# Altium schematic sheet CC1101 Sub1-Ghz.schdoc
size 297 x 209 mm; Symbol: Drawing-Symbol_A4; @Project Name: Hưhwwuey; @Page Count: 5; @Update Date: 2026-10-18; @Create Date: 2026-10-18; @Schematic Name: Schematic1; @Page No: 5; @Page Name: P1; Company: EasyEDA.com; Version: V1.0; Page Size: A4; Device: Drawing-Symbol_A4; @Create Time: 09:30:38; @Update Time: 09:30:38; Border: 1; Width: 1170; Height: 825; Region Start: 1; X Region Count: 6; Y Region Count: 4; Blade Width: 10; Title Block Position: 3; @Board Name: Board1
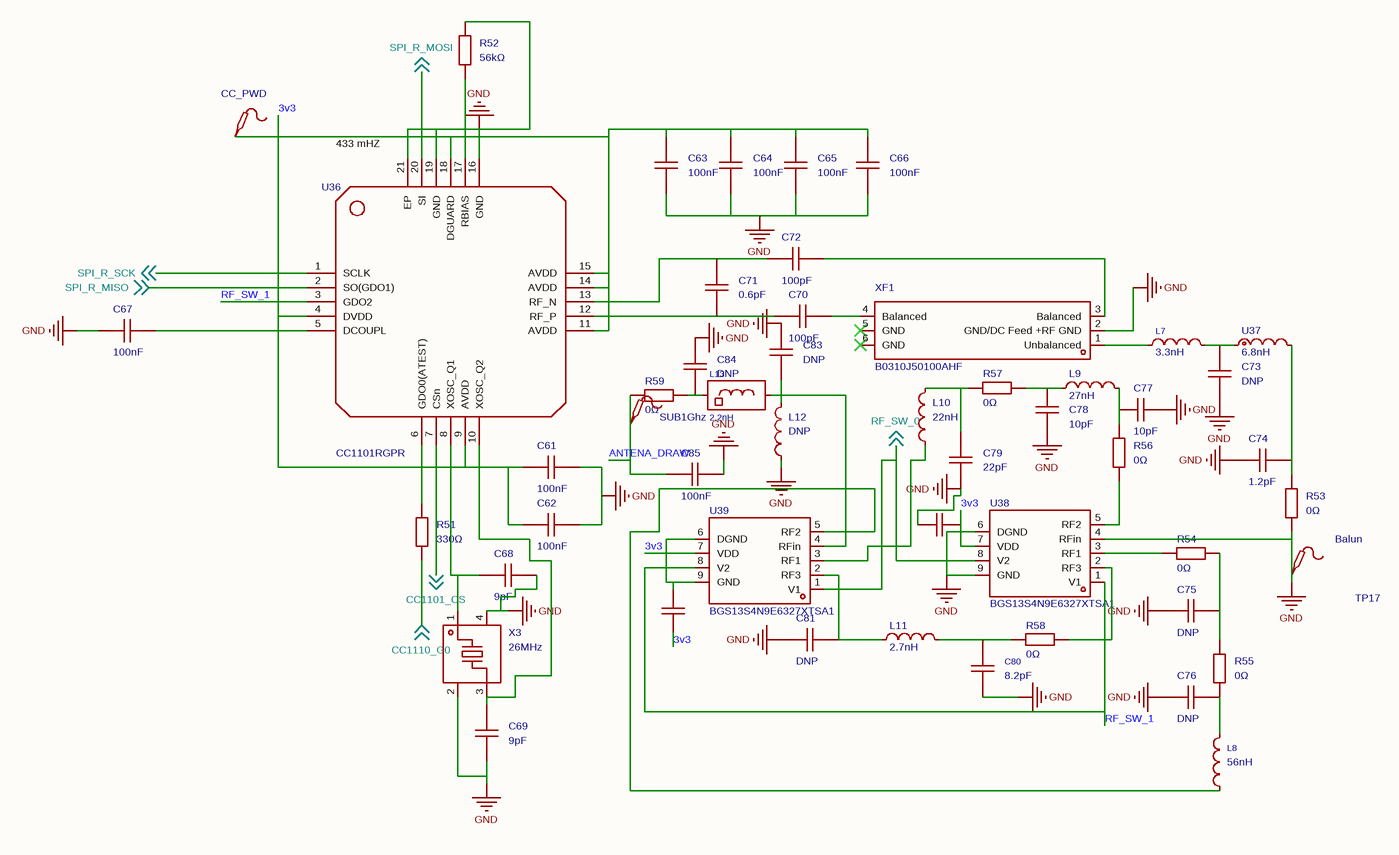
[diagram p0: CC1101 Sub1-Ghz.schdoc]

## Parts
C61  100nF  [C0402]
C62  100nF  [C0402]
C63  100nF  [C0402]
C64  100nF  [C0402]
C65  100nF  [C0402]
C66  100nF  [C0402]
C67  100nF  [C0402]
C68  9pF  [C0402]
C69  9pF  [C0402]
C70  100pF  [C0603]
C71  0.6pF  [C0201]
C72  100pF  [C0603]
C73  DNP  [C0402]
C74  1.2pF  [C0402]
C75  DNP  [C0402]
C76  DNP  [C0402]
C77  10pF  [C0603]
C78  10pF  [C0603]
C79  22pF  [C0402]
C80  8.2pF  [C0402]
C81  DNP  [C0402]
C82  10nF  [C0402]  (value not drawn)
C83  DNP  [C0402]
C84  DNP  [C0402]
C85  100nF  [C0402]
C86  10nF  [C0402]  (value not drawn)
L7  3.3nH  [L0402]
L8  56nH  [L0402]
L9  27nH  [L0402-RD]
L10  22nH  [L0402]
L11  2.7nH  [L0402]
L12  DNP  [L0402]
L13  2.2nH  [IND-SMD_L1.0-W0.5_LQG15HN1N6B02D]
R51  330Ω  [R0402]
R52  56kΩ  [R0402]
R53  0Ω  [R0201]
R54  0Ω  [R0402]
R55  0Ω  [R0402]
R56  0Ω  [R0402]
R57  0Ω  [R0402]
R58  0Ω  [R0402]
R59  0Ω  [R0402]
TP16  CC_PWD  [Test-Point-0.5mm]
TP17  Balun  [Test-Point-0.5mm]
TP18  SUB1Ghz  [Test-Point-0.5mm]
U36  CC1101RGPR  [QFN-20_L4.0-W4.0-P0.5-TL-EP]
U37  6.8nH  [L0402-RD]
U38  BGS13S4N9E6327XTSA1  [TSNP-9_L1.1-W1.1-P0.40-BL]
U39  BGS13S4N9E6327XTSA1  [TSNP-9_L1.1-W1.1-P0.40-BL]
X3  26MHz  [CRYSTAL-SMD_4P-L3.2-W2.5-BL]
XF1  B0310J50100AHF  [XFMR-SMD_6P-L2.1-W1.3-P0.65-BL]

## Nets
GND: C61.1 C62.1 C63.2 C64.2 C65.2 C66.2 C67.2 C68.2 C69.1 C73.2 C74.1 C75.2 C76.2 C77.2 C78.2 C79.1 C80.2 C81.1 C82.2 C83.2 C84.1 C85.1 L12.1 R52.2 R53.1 TP17.1 U36.16(GND) U36.19(GND) U36.21(EP) U38.4(RFin) U38.6(DGND) U38.9(GND) X3.2(GND) X3.4(GND) XF1.2(GND/DC_Feed_+RF_GND)
3v3: C61.2 C62.2 C63.1 C64.1 C65.1 C66.1 C82.1 C86.2 TP16.1 U36.4(DVDD) U36.9(AVDD) U36.11(AVDD) U36.14(AVDD) U36.15(AVDD) U36.18(DGUARD) U38.7(VDD) U39.7(VDD)
ANTENA_DRAW: C85.2 R59.2 TP18.1
CC1101_CS: U36.7(CSn) ; off-sheet CC1101_CS
CC1110_G0: R51.1 ; off-sheet CC1110_G0
RF_SW_0: U38.8(V2) U39.1(V1) ; off-sheet RF_SW_0
RF_SW_1: U36.3(GDO2) U38.1(V1) U39.8(V2)
SPI_R_MISO: U36.2(SO(GDO1)) ; off-sheet SPI_R_MISO
SPI_R_MOSI: U36.20(SI) ; off-sheet SPI_R_MOSI
SPI_R_SCK: U36.1(SCLK) ; off-sheet SPI_R_SCK
NetC67_1: C67.1 U36.5(DCOUPL)
NetC68_1: C68.1 U36.8(XOSC_Q1) X3.1
NetC69_2: C69.2 U36.10(XOSC_Q2) X3.3
NetC70_1: C70.1 C71.2 U36.12(RF_P)
NetC70_2: C70.2 XF1.4(Balanced)
NetC71_1: C71.1 C72.1 U36.13(RF_N)
NetC72_2: C72.2 XF1.3(Balanced)
NetC73_1: C73.1 L7.2 U37.1
NetC74_2: C74.2 R53.2 U37.2
NetC75_1: C75.1 R54.2 R55.2
NetC76_1: C76.1 L8.2 R55.1
NetC77_1: C77.1 L9.2 R56.2
NetC78_1: C78.1 L9.1 R57.1
NetC79_2: C79.2 L10.2 R57.2
NetC80_1: C80.1 L11.2 R58.2
NetC81_2: C81.2 L11.1 U39.2(RF3)
NetC83_1: C83.1 L12.2 L13.2 U39.4(RFin)
NetC84_2: C84.2 L13.1 R59.1
NetC86_1: C86.1 U39.6(DGND) U39.9(GND)
NetL7_1: L7.1 XF1.1(Unbalanced)
NetL8_1: L8.1 U39.5(RF2)
NetL10_1: L10.1 U39.3(RF1)
NetR51_2: R51.2 U36.6(GDO0(ATEST))
NetR52_1: R52.1 U36.17(RBIAS)
NetR54_1: R54.1 U38.3(RF1)
NetR56_1: R56.1 U38.5(RF2)
NetR58_1: R58.1 U38.2(RF3)

Not connected (* = marked no-connect by the designer): XF1 5(GND)* 6(GND)*

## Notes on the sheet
- (near U36) 433 mHZ

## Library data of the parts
C61-C67 C85 = CAP_0402: Symbol: CAP_OLD; 3D Model: b7d13df3e9464d7a99d0651d1a5b4d570819f05c4eef4c71ace90d822a990e87; 3D Model Transform: 39.37,19.685,0,0,0,0,0,0,0; ConvertToPcb: yes; ModelName: C0402_L1.0-W0.5-H0.5
C68 C69 = GRM1555C1H9R0CA01D: Capacitance: Voltage Rated: Temperature Coefficient:; Manufacturer: muRata(村田); AddInBom: yes; ModelId: b7d13df3e9464d7a99d0651d1a5b4d570819f05c4eef4c71ace90d822a990e87; ModelName: C0402_L1.0-W0.5-H0.5; ModelTransform: 39.37,19.685,0,0,0,0,0,0,0
C70 C72 = C0603C101K8HACAUTO: Capacitance: Tolerance:±10% Tolerance:±10% Voltage Rated: Temperature Coefficient:; Manufacturer: KEMET(基美); AddInBom: yes; ModelId: 624118aa3cc7497086c383c2d72e08520819f05c4eef4c71ace90d822a990e87; ModelName: C0603_L1.6-W0.8-H0.8; ModelTransform: 62.992,31.496,0,0,0,0,0,0,0; Tolerance: ±10%
C71 = C0603NP0608BGTS: Capacitance:0.6pF Voltage Rating:50V Temperature Coefficient:NP0; Manufacturer: DARFON(达方); AddInBom: yes; ModelId: c3e75c3d90204c70b153866ab54c789f0819f05c4eef4c71ace90d822a990e87; ModelName: C0201_L0.6-W0.3-H0.3; ModelTransform: 23.622,11.811,0,0,0,0,0,0,0; Voltage Rating: 50V; Temperature Coefficient: NP0
C73 C75 C81 C83 C84 = CAP_0402: Symbol: CAP_OLD; 3D Model: b7d13df3e9464d7a99d0651d1a5b4d570819f05c4eef4c71ace90d822a990e87; 3D Model Transform: 39.37,19.685,0,0,0,0,0,0,0; Add into BOM: no; ConvertToPcb: yes; ModelName: C0402_L1.0-W0.5-H0.5
C74 = GRM1555C1H1R2BA01J: Capacitance:1.2pF Voltage Rating:50V; Manufacturer: muRata(村田); AddInBom: yes; ModelId: b7d13df3e9464d7a99d0651d1a5b4d570819f05c4eef4c71ace90d822a990e87; ModelName: C0402_L1.0-W0.5-H0.5; ModelTransform: 39.37,19.685,0,0,0,0,0,0,0; Voltage Rating: 50V
C76 = CAP_0402: Symbol: CAP_OLD; Add into BOM: no; 3D Model: b7d13df3e9464d7a99d0651d1a5b4d570819f05c4eef4c71ace90d822a990e87; 3D Model Transform: 39.37,19.685,0,0,0,0,0,0,0; ConvertToPcb: yes; ModelName: C0402_L1.0-W0.5-H0.5
C77 C78 = CC0603JRNPO9BN100: Capacitance:10pF Tolerance:±5% Tolerance:±5% Voltage Rating:50V Temperature Coefficient:NP0; Manufacturer: YAGEO(国巨); AddInBom: yes; ModelId: 624118aa3cc7497086c383c2d72e08520819f05c4eef4c71ace90d822a990e87; ModelName: C0603_L1.6-W0.8-H0.8; ModelTransform: 62.992,31.496,0,0,0,0,0,0,0; Tolerance: ±5%; Voltage Rating: 50V; Temperature Coefficient: NP0
C79 = GRM1555C1H220JA01D: Capacitance:22pF Tolerance:±5% Tolerance:±5% Voltage Rating:50V Temperature Coefficient:C0G; Manufacturer: muRata(村田); AddInBom: yes; ModelId: b7d13df3e9464d7a99d0651d1a5b4d570819f05c4eef4c71ace90d822a990e87; ModelName: C0402_L1.0-W0.5-H0.5; ModelTransform: 39.37,19.685,0,0,0,0,0,0,0; Tolerance: ±5%; Voltage Rating: 50V; Temperature Coefficient: C0G
C80 = 0402N8R2B500CT: Capacitance: Voltage Rated: Temperature Coefficient:; Manufacturer: Walsin(华新科); AddInBom: yes; ModelId: b7d13df3e9464d7a99d0651d1a5b4d570819f05c4eef4c71ace90d822a990e87; ModelName: C0402_L1.0-W0.5-H0.5; ModelTransform: 39.37,19.685,0,0,0,0,0,0,0
C82 C86 = CC0402KRX7R9BB103: Capacitance:10nF Tolerance:±10% Tolerance:±10% Voltage Rating:50V Temperature Coefficient:X7R; Manufacturer: YAGEO(国巨); 3D Model: b7d13df3e9464d7a99d0651d1a5b4d570819f05c4eef4c71ace90d822a990e87; 3D Model Transform: 39.37,19.685,0,0,0,0,0,0,0; Tolerance: ±10%; Voltage Rating: 50V; Temperature Coefficient: X7R; AddInBom: yes; ModelName: C0402_L1.0-W0.5-H0.5
L7 = LQG15HS3N3B02D: Inductance:3.3nH Tolerance:- Tolerance:- Current Rating:800mA Current - Saturation (Isat):- DC Resistance(DCR):125mΩ Q @ Frequency:8@100MHz Frequency - Self Resonant:6GHz Type:Multilayer inductor; Manufacturer: muRata(村田); AddInBom: yes; ModelId: aef00b1603224fd68a96e37121ccc9160819f05c4eef4c71ace90d822a990e87; ModelName: L0402_L1.0-W0.5-H0.5_BEAD; ModelTransform: 39.37,19.685,0,0,0,0,0,0.0005,0; Current Rating: 800mA; DC Resistance(DCR): 125mΩ; Frequency - Self Resonant: 6GHz
L8 = SDCL1005C56NJTDF: Inductance:56nH Tolerance:±5% Tolerance:±5% Current Rating:200mA Current - Saturation (Isat):- DC Resistance(DCR):1.2Ω Q @ Frequency:8@100MHz Frequency - Self Resonant:750MHz Ratings:-; Manufacturer: Sunlord(顺络); AddInBom: yes; ModelId: aef00b1603224fd68a96e37121ccc9160819f05c4eef4c71ace90d822a990e87; ModelName: L0402_L1.0-W0.5-H0.5_BEAD; ModelTransform: 39.37,19.685,0,0,0,0,0,0.0005,0; Tolerance: ±5%; Current Rating: 200mA; DC Resistance(DCR): 1.2Ω; Frequency - Self Resonant: 750MHz
L9 = LQG15HS27NJ02D: Inductance:27nH Tolerance:±5% Tolerance:±5% Current Rating:350mA Current - Saturation (Isat):- DC Resistance(DCR):460mΩ Q @ Frequency:8@100MHz Frequency - Self Resonant:1.7GHz Ratings:-; Manufacturer: muRata(村田); AddInBom: yes; ModelId: af8519f297ad48beac83bdc898afdb0a0819f05c4eef4c71ace90d822a990e87; ModelTransform: 40.1574,20.4724,0,0,0,0,0,0,0; Tolerance: ±5%; Current Rating: 350mA; DC Resistance(DCR): 460mΩ; Frequency - Self Resonant: 1.7GHz
L10 = LQG15HS22NJ02D: Inductance:22nH Tolerance:±5% Tolerance:±5% Current Rating:350mA Current - Saturation (Isat):- DC Resistance(DCR):420mΩ Q @ Frequency:8@100MHz Frequency - Self Resonant:1.9GHz; Manufacturer: muRata(村田); AddInBom: yes; ModelId: aef00b1603224fd68a96e37121ccc9160819f05c4eef4c71ace90d822a990e87; ModelName: L0402_L1.0-W0.5-H0.5_BEAD; ModelTransform: 39.37,19.685,0,0,0,0,0,0.0005,0; Tolerance: ±5%; Current Rating: 350mA; DC Resistance(DCR): 420mΩ; Frequency - Self Resonant: 1.9GHz
L11 = LQG15HS2N7S02D: Inductance:2.7nH Tolerance:- Tolerance:- Current Rating:800mA Current - Saturation (Isat):- DC Resistance(DCR):150mΩ Q @ Frequency:8@100MHz Frequency - Self Resonant:6GHz Type:Multilayer inductor; Manufacturer: muRata(村田); AddInBom: yes; ModelId: aef00b1603224fd68a96e37121ccc9160819f05c4eef4c71ace90d822a990e87; ModelName: L0402_L1.0-W0.5-H0.5_BEAD; ModelTransform: 39.37,19.685,0,0,0,0,0,0.0005,0; Current Rating: 800mA; DC Resistance(DCR): 150mΩ; Frequency - Self Resonant: 6GHz
L12 = LQG15HS2N7S02D: Inductance:2.7nH Tolerance:- Tolerance:- Current Rating:800mA Current - Saturation (Isat):- DC Resistance(DCR):150mΩ Q @ Frequency:8@100MHz Frequency - Self Resonant:6GHz Type:Multilayer inductor; Manufacturer: muRata(村田); Add into BOM: no; ConvertToPcb: yes; ModelId: aef00b1603224fd68a96e37121ccc9160819f05c4eef4c71ace90d822a990e87; ModelName: L0402_L1.0-W0.5-H0.5_BEAD; ModelTransform: 39.37,19.685,0,0,0,0,0,0.0005,0; Current Rating: 800mA; DC Resistance(DCR): 150mΩ; Frequency - Self Resonant: 6GHz
L13 = LQG15HS2N2S02D: Inductance:2.2nH Tolerance:- Tolerance:- Current Rating:900mA Current - Saturation (Isat):- DC Resistance(DCR):120mΩ Q @ Frequency:8@100MHz Frequency - Self Resonant:6GHz Type:Multilayer inductor; Manufacturer: muRata(村田); AddInBom: yes; ModelId: f5056074800743309c4ad3a5d78f501d0819f05c4eef4c71ace90d822a990e87; ModelTransform: 39.37,19.685,0,180,0,0,0,0,0; Current Rating: 900mA; DC Resistance(DCR): 120mΩ; Frequency - Self Resonant: 6GHz
R51 = WR04X331JTL: Type:Thick Film Resistor Resistance:330Ω Tolerance:±5% Tolerance:±5% Power(Watts):62.5mW Voltage-Supply(Max):50V Temperature Coefficient:±100ppm/℃ Temperature Coefficient:±100ppm/℃ Operating Temperature:-55℃~+155℃ Operating Temperature:-55℃~+155℃; Manufacturer: Walsin(华新科); AddInBom: yes; ModelId: efdecb7dae4442949d28eecaf748420f0819f05c4eef4c71ace90d822a990e87; ModelName: R0402_L1.0-W0.5-H0.4; ModelTransform: 39.37,19.685,0,0,0,0,0,0,0; Tolerance: ±5%; Power(Watts): 62.5mW; Voltage-Supply(Max): 50V
R52 = WR04X5602FTL: Type:Thick Film Resistor Resistance:56kΩ Tolerance:±1% Tolerance:±1% Power(Watts):62.5mW Voltage-Supply(Max):50V Temperature Coefficient:±100ppm/℃ Temperature Coefficient:±100ppm/℃ Operating Temperature:-55℃~+155℃ Operating Temperature:-55℃~+155℃; Manufacturer: Walsin(华新科); AddInBom: yes; ModelId: efdecb7dae4442949d28eecaf748420f0819f05c4eef4c71ace90d822a990e87; ModelName: R0402_L1.0-W0.5-H0.4; ModelTransform: 39.37,19.685,0,0,0,0,0,0,0; Tolerance: ±1%; Power(Watts): 62.5mW; Voltage-Supply(Max): 50V
R53 = WR02X000PAL: Type:Thick Film Resistor Resistance:0Ω Tolerance:- Tolerance:- Power(Watts):50mW Voltage-Supply(Max):25V Temperature Coefficient:- Temperature Coefficient:- Operating Temperature:-55℃~+125℃ Operating Temperature:-55℃~+125℃; Manufacturer: Walsin(华新科); AddInBom: yes; ModelId: d3c6830bf3df48b598874c11a7d9c8170819f05c4eef4c71ace90d822a990e87; ModelName: R0201_L0.6-W0.3-H0.3; ModelTransform: 23.622,11.811,0,0,0,0,0,-0.0005,0; Power(Watts): 50mW; Voltage-Supply(Max): 25V
R54-R59 = WR04X000PTL: Type:Thick Film Resistor Resistance:0Ω Tolerance:- Tolerance:- Power(Watts):62.5mW Voltage-Supply(Max):50V Temperature Coefficient:-200ppm/℃~+400ppm/℃ Temperature Coefficient:-200ppm/℃~+400ppm/℃ Operating Temperature:-55℃~+155℃ Operating Temperature:-55℃~; Manufacturer: Walsin(华新科); AddInBom: yes; ModelId: efdecb7dae4442949d28eecaf748420f0819f05c4eef4c71ace90d822a990e87; ModelName: R0402_L1.0-W0.5-H0.4; ModelTransform: 39.37,19.685,0,0,0,0,0,0,0; Power(Watts): 62.5mW; Voltage-Supply(Max): 50V
TP16-TP18 = Test-Point: Test Point 测试点; AddInBom: yes
U36 = CC1101RGPR: Frequency Range:387MHz~464MHz；300MHz~348MHz；779MHz~928MHz Frequency Range:387MHz~464MHz；300MHz~348MHz；779MHz~928MHz Interface:SPI Voltage - Supply:1.8V~3.6V Voltage - Supply:1.8V~3.6V Applications:ISM Output Power:12dBm Data Rate:500Kbps Current Of Transm; Manufacturer: TI(德州仪器); AddInBom: yes; ModelId: a5a02adac653411a975ad6ce66ef70860819f05c4eef4c71ace90d822a990e87; ModelName: QFN-20_L4.0-W4.0-H0.8-P0.50; ModelTransform: 157.48,157.481,0,0,0,0,0,0,0; Interface: SPI; Output Power: 12dBm; Current Of Transmitting: 34.2mA; Sensitivity: -112dBm; Receive Current: 15.7mA; Typical Application Frequency: 433MHz；315MHz；868MHz；915MHz
U37 = LQG15HS6N8G02D: Inductance: Tolerance:±2% Tolerance:±2% Rated Current: Saturation Current (Isat):- DC Resistance (DCR): Q @ Freq:8@100MHz Frequency - Self Resonant: Ratings:; Manufacturer: muRata(村田); AddInBom: yes; ModelId: af8519f297ad48beac83bdc898afdb0a0819f05c4eef4c71ace90d822a990e87; ModelTransform: 40.1574,20.4724,0,0,0,0,0,0,0; Tolerance: ±2%
U38 U39 = BGS13S4N9E6327XTSA1: AddInBom: yes; ModelId: 0e5519ca097d4d6bb25208b6aa9ba91c0819f05c4eef4c71ace90d822a990e87; ModelName: TSNP-9_L1.1-W1.1-H0.4-P0.40-BL; ModelTransform: 43.307,43.307,0,0,0,0,0,0,0
X3 = 3225 26M 9PF 10PPM: Frequency:26MHz Normal temperature Frequency Tolerance:±10ppm Normal temperature Frequency Tolerance:±10ppm Load Capacitance:9pF Frequency Stability:±30ppm Frequency Stability:±30ppm Operating Temperature:-20℃~+70℃ Operating Temperature:-20℃~+70℃; Manufacturer: SOSET(索斯特); AddInBom: yes; ModelId: a2b47bc5d32f4dfd996128e047b549a00819f05c4eef4c71ace90d822a990e87; ModelTransform: 125.984,98.425,0,0,0,0,0,0,0; Normal temperature Frequency Tolerance: ±10ppm; Load Capacitance: 9pF; Frequency Stability: ±30ppm
XF1 = B0310J50100AHF: Frequency Range:300MHz~1GHz Frequency Range:300MHz~1GHz Impedance - Unbalanced/Balanced:50Ω:100Ω Common Mode Rejection Ratio(CMRR):9dB Insertion Loss (Max):0.8dB Phase Difference:38° Amplitude Balance (Max):2.5dB Return Loss(Min):8.1dB Operating Temperatu; Manufacturer: TTM Technologies, Inc.; Symbol: B0310J50100AHF_C5160223; AddInBom: yes; ModelId: 7629c7597d774485bb8b8d478730088a0819f05c4eef4c71ace90d822a990e87; ModelName: XFMR-SMD_6P-L2.1-W1.3-H0.7-P0.65-BL; ModelTransform: 80.3148,50.7873,0,180,0,0,0,0,0; Common Mode Rejection Ratio(CMRR): 9dB; Insertion Loss (Max): 0.8dB; Phase Difference: 38°; Amplitude Balance (Max): 2.5dB; Return Loss(Min): 8.1dB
